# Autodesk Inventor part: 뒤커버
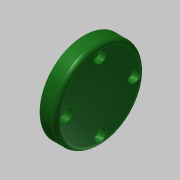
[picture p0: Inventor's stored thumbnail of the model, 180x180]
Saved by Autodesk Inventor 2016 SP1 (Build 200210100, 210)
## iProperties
Created: 2015-11
Part Number: 뒤커버
Material: 알루미늄 6061
Document SubType Name: Modeling
Designer: mduedu
Density: 1 g/cm^3
Appearance: 매끄러움 - 짙은 산림 녹색
Author: mduedu
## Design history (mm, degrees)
sketch "스케치5"
  geometry: C1 r 30 at (0, 0); 2 further points
  constraints: 2 coincident, 1 centre point
  dimensions: "d66" = 60 diameter of C1
extrude "돌출2" new body sketch "스케치5" distance "d67" = 11; taper "d68" = 0 deg
sketch "스케치6"
  geometry: C1 r 16 at (0, 0); 1 further point
  constraints: 1 centre point, 1 coincident
  dimensions: "d69" = 32 diameter of C1
extrude "돌출3" join sketch "스케치6" distance "d70" = 3; taper "d71" = 0 deg
hole "구멍5" diameter "d74" = 25; stored, may be unused: countersink angle "d78" = 90 deg, drill point angle "d80" = 0 deg; dims "d72" = 10, "d73" = 10, "d75" = 6, "d76" = 4, "d77" = 2, "d79" = 10
fillet "모깎기8" dims "d82" = 3
fillet "모깎기9" dims "d83" = 3
fillet "모깎기10" dims "d84" = 0.3
sketch "스케치7" dims "d85" = 46
  geometry: 3 further points
  constraints: 2 vertical alignment, 1 coincident, 2 other
hole "구멍6" sketch "스케치7" at (0, 23) diameter "d86" = 4.5; stored, may be unused: countersink angle "d90" = 90 deg, drill point angle "d92" = 0 deg; dims "d87" = 6, "d88" = 8, "d89" = 4.6, "d91" = 10
node "솔리드2"
pattern_circular "원형 패턴3" dims angle "d94" = 360 deg
